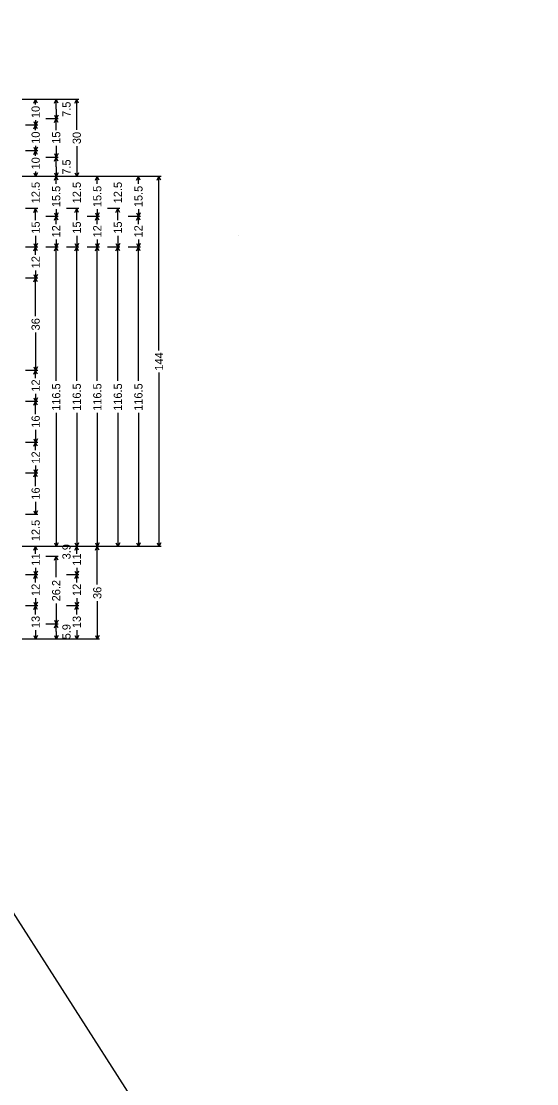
# Model space of a CAD drawing. Extents: x 667331 to 731245, y 738830 to 753817.
# Drawn here: x 723929 to 724230, y 748814 to 749434 of the extents above; entities that cross this region are included whole.
import ezdxf

# ---------------------------------------------------------------- set-up
doc = ezdxf.new("R2010")
doc.units = 0
doc.layers.add('R_SIGN', color=7, linetype='Continuous')

msp = doc.modelspace()

# ---------------------------------------------------------------- linework, layer by layer
at = {"layer": 'R_SIGN'}
for p, q in [((725910.64, 745814.78), (722956.13, 750422.85)), ((723962.15, 749388.12), (723929.15, 749388.12)), ((723938.15, 749388.12), (723930.95, 749388.12)), ((723935.87, 749385.97), (723936.95, 749388.12)), ((723936.95, 749385.15), (723936.95, 749388.12)), ((723938.02, 749385.97), (723936.95, 749388.12)), ((723950.15, 749388.12), (723942.95, 749388.12)), ((723947.87, 749385.97), (723948.95, 749388.12)), ((723948.95, 749382.49), (723948.95, 749388.12)), ((723950.02, 749385.97), (723948.95, 749388.12)), ((723959.87, 749385.97), (723960.95, 749388.12)), ((723960.95, 749370.36), (723960.95, 749388.12)), ((723962.02, 749385.97), (723960.95, 749388.12)), ((723947.87, 749379.02), (723948.95, 749376.87)), ((723948.95, 749382.49), (723948.95, 749376.87)), ((723950.02, 749379.02), (723948.95, 749376.87)), ((723938.15, 749373.12), (723930.95, 749373.12)), ((723935.87, 749375.27), (723936.95, 749373.12)), ((723935.87, 749370.97), (723936.95, 749373.12)), ((723936.95, 749376.09), (723936.95, 749373.12)), ((723938.02, 749375.27), (723936.95, 749373.12)), ((723936.95, 749370.15), (723936.95, 749373.12)), ((723938.02, 749370.97), (723936.95, 749373.12)), ((723950.15, 749376.87), (723942.95, 749376.87)), ((723947.87, 749374.72), (723948.95, 749376.87)), ((723948.95, 749370.16), (723948.95, 749376.87)), ((723950.02, 749374.72), (723948.95, 749376.87)), ((723936.95, 749361.09), (723936.95, 749358.12)), ((723948.95, 749361.08), (723948.95, 749354.37)), ((723960.95, 749360.88), (723960.95, 749343.12)), ((723938.15, 749358.12), (723930.95, 749358.12)), ((723938.15, 749358.12), (723930.95, 749358.12)), ((723935.87, 749360.27), (723936.95, 749358.12)), ((723935.87, 749355.97), (723936.95, 749358.12)), ((723938.02, 749360.27), (723936.95, 749358.12)), ((723936.95, 749355.15), (723936.95, 749358.12)), ((723938.02, 749355.97), (723936.95, 749358.12)), ((723950.15, 749354.37), (723942.95, 749354.37)), ((723950.15, 749354.37), (723942.95, 749354.37)), ((723947.87, 749356.52), (723948.95, 749354.37)), ((723947.87, 749352.22), (723948.95, 749354.37)), ((723950.02, 749356.52), (723948.95, 749354.37)), ((723948.95, 749348.74), (723948.95, 749354.37)), ((723950.02, 749352.22), (723948.95, 749354.37)), ((723948.95, 749348.74), (723948.95, 749343.12)), ((724010.15, 749343.12), (723929.15, 749343.12)), ((723962.15, 749343.12), (723929.15, 749343.12)), ((723938.15, 749343.12), (723930.95, 749343.12)), ((723938.15, 749343.12), (723930.95, 749343.12)), ((723935.87, 749345.27), (723936.95, 749343.12)), ((723936.95, 749346.09), (723936.95, 749343.12)), ((723938.02, 749345.27), (723936.95, 749343.12)), ((723950.15, 749343.12), (723942.95, 749343.12)), ((723950.15, 749343.12), (723942.95, 749343.12)), ((723947.87, 749345.27), (723948.95, 749343.12)), ((723947.87, 749340.97), (723948.95, 749343.12)), ((723950.02, 749345.27), (723948.95, 749343.12)), ((723948.95, 749338.94), (723948.95, 749343.12)), ((723950.02, 749340.97), (723948.95, 749343.12)), ((723962.15, 749343.12), (723954.95, 749343.12)), ((723959.87, 749345.27), (723960.95, 749343.12)), ((723962.02, 749345.27), (723960.95, 749343.12)), ((723974.15, 749343.12), (723966.95, 749343.12)), ((723971.87, 749340.97), (723972.95, 749343.12)), ((723972.95, 749338.94), (723972.95, 749343.12)), ((723974.02, 749340.97), (723972.95, 749343.12)), ((723986.15, 749343.12), (723978.95, 749343.12)), ((723998.15, 749343.12), (723990.95, 749343.12)), ((723995.87, 749340.97), (723996.95, 749343.12)), ((723996.95, 749338.94), (723996.95, 749343.12)), ((723998.02, 749340.97), (723996.95, 749343.12)), ((724007.87, 749340.97), (724008.95, 749343.12)), ((724008.95, 749241.56), (724008.95, 749343.12)), ((724010.02, 749340.97), (724008.95, 749343.12)), ((723938.15, 749324.41), (723930.95, 749324.41)), ((723935.87, 749322.26), (723936.95, 749324.41)), ((723936.95, 749317.7), (723936.95, 749324.41)), ((723938.02, 749322.26), (723936.95, 749324.41)), ((723948.95, 749324.08), (723948.95, 749319.91)), ((723962.15, 749324.41), (723954.95, 749324.41)), ((723959.87, 749322.26), (723960.95, 749324.41)), ((723960.95, 749317.7), (723960.95, 749324.41)), ((723962.02, 749322.26), (723960.95, 749324.41)), ((723972.95, 749324.08), (723972.95, 749319.91)), ((723986.15, 749324.41), (723978.95, 749324.41)), ((723983.87, 749322.26), (723984.95, 749324.41)), ((723984.95, 749317.7), (723984.95, 749324.41)), ((723986.02, 749322.26), (723984.95, 749324.41)), ((723996.95, 749324.08), (723996.95, 749319.91)), ((723950.15, 749319.91), (723942.95, 749319.91)), ((723947.87, 749322.05), (723948.95, 749319.91)), ((723947.87, 749317.76), (723948.95, 749319.91)), ((723950.02, 749322.05), (723948.95, 749319.91)), ((723948.95, 749315.42), (723948.95, 749319.91)), ((723950.02, 749317.76), (723948.95, 749319.91)), ((723974.15, 749319.91), (723966.95, 749319.91)), ((723971.87, 749322.05), (723972.95, 749319.91)), ((723971.87, 749317.76), (723972.95, 749319.91)), ((723974.02, 749322.05), (723972.95, 749319.91)), ((723972.95, 749315.42), (723972.95, 749319.91)), ((723974.02, 749317.76), (723972.95, 749319.91)), ((723998.15, 749319.91), (723990.95, 749319.91)), ((723995.87, 749322.05), (723996.95, 749319.91)), ((723995.87, 749317.76), (723996.95, 749319.91)), ((723998.02, 749322.05), (723996.95, 749319.91)), ((723996.95, 749315.42), (723996.95, 749319.91)), ((723998.02, 749317.76), (723996.95, 749319.91)), ((723936.95, 749308.61), (723936.95, 749301.91)), ((723948.95, 749306.39), (723948.95, 749301.91)), ((723960.95, 749308.61), (723960.95, 749301.91)), ((723972.95, 749306.39), (723972.95, 749301.91)), ((723984.95, 749308.61), (723984.95, 749301.91)), ((723996.95, 749306.39), (723996.95, 749301.91)), ((724055.45, 749308.62), (724055.45, 749308.62)), ((724055.45, 749308.62), (724055.45, 749308.62)), ((724055.45, 749308.62), (724055.45, 749308.62)), ((724055.45, 749308.62), (724055.45, 749308.62)), ((723938.15, 749301.91), (723930.95, 749301.91)), ((723935.87, 749304.05), (723936.95, 749301.91)), ((723935.87, 749299.76), (723936.95, 749301.91)), ((723938.02, 749304.05), (723936.95, 749301.91)), ((723936.95, 749297.42), (723936.95, 749301.91)), ((723938.02, 749299.76), (723936.95, 749301.91)), ((723950.15, 749301.91), (723942.95, 749301.91)), ((723950.15, 749301.91), (723942.95, 749301.91)), ((723947.87, 749304.05), (723948.95, 749301.91)), ((723947.87, 749299.76), (723948.95, 749301.91)), ((723950.02, 749304.05), (723948.95, 749301.91)), ((723948.95, 749223.87), (723948.95, 749301.91)), ((723950.02, 749299.76), (723948.95, 749301.91)), ((723962.15, 749301.91), (723954.95, 749301.91)), ((723962.15, 749301.91), (723954.95, 749301.91)), ((723959.87, 749304.05), (723960.95, 749301.91)), ((723959.87, 749299.76), (723960.95, 749301.91)), ((723962.02, 749304.05), (723960.95, 749301.91)), ((723960.95, 749223.87), (723960.95, 749301.91)), ((723962.02, 749299.76), (723960.95, 749301.91)), ((723974.15, 749301.91), (723966.95, 749301.91)), ((723974.15, 749301.91), (723966.95, 749301.91)), ((723971.87, 749304.05), (723972.95, 749301.91)), ((723971.87, 749299.76), (723972.95, 749301.91)), ((723974.02, 749304.05), (723972.95, 749301.91)), ((723972.95, 749223.87), (723972.95, 749301.91)), ((723974.02, 749299.76), (723972.95, 749301.91)), ((723986.15, 749301.91), (723978.95, 749301.91)), ((723986.15, 749301.91), (723978.95, 749301.91)), ((723983.87, 749304.05), (723984.95, 749301.91)), ((723983.87, 749299.76), (723984.95, 749301.91)), ((723986.02, 749304.05), (723984.95, 749301.91)), ((723984.95, 749223.87), (723984.95, 749301.91)), ((723986.02, 749299.76), (723984.95, 749301.91)), ((723998.15, 749301.91), (723990.95, 749301.91)), ((723998.15, 749301.91), (723990.95, 749301.91)), ((723995.87, 749304.05), (723996.95, 749301.91)), ((723995.87, 749299.76), (723996.95, 749301.91)), ((723998.02, 749304.05), (723996.95, 749301.91)), ((723996.95, 749223.87), (723996.95, 749301.91)), ((723998.02, 749299.76), (723996.95, 749301.91)), ((723935.87, 749286.05), (723936.95, 749283.91)), ((723936.95, 749288.39), (723936.95, 749283.91)), ((723938.02, 749286.05), (723936.95, 749283.91)), ((723938.15, 749283.91), (723930.95, 749283.91)), ((723935.87, 749281.76), (723936.95, 749283.91)), ((723936.95, 749261.69), (723936.95, 749283.91)), ((723938.02, 749281.76), (723936.95, 749283.91)), ((723936.95, 749252.13), (723936.95, 749229.91)), ((723935.87, 749232.05), (723936.95, 749229.91)), ((723938.02, 749232.05), (723936.95, 749229.91)), ((723938.15, 749229.91), (723930.95, 749229.91)), ((723935.87, 749227.76), (723936.95, 749229.91)), ((723936.95, 749225.42), (723936.95, 749229.91)), ((723938.02, 749227.76), (723936.95, 749229.91)), ((724008.95, 749228.68), (724008.95, 749127.12)), ((723938.15, 749211.91), (723930.95, 749211.91)), ((723935.87, 749214.05), (723936.95, 749211.91)), ((723935.87, 749209.76), (723936.95, 749211.91)), ((723936.95, 749216.39), (723936.95, 749211.91)), ((723938.02, 749214.05), (723936.95, 749211.91)), ((723936.95, 749204.47), (723936.95, 749211.91)), ((723938.02, 749209.76), (723936.95, 749211.91)), ((723948.95, 749205.16), (723948.95, 749127.12)), ((723960.95, 749205.16), (723960.95, 749127.12)), ((723972.95, 749205.16), (723972.95, 749127.12)), ((723984.95, 749205.16), (723984.95, 749127.12)), ((723996.95, 749205.16), (723996.95, 749127.12)), ((723936.95, 749195.34), (723936.95, 749187.91)), ((723938.15, 749187.91), (723930.95, 749187.91)), ((723935.87, 749190.05), (723936.95, 749187.91)), ((723935.87, 749185.76), (723936.95, 749187.91)), ((723938.02, 749190.05), (723936.95, 749187.91)), ((723936.95, 749183.42), (723936.95, 749187.91)), ((723938.02, 749185.76), (723936.95, 749187.91)), ((723936.95, 749174.39), (723936.95, 749169.91)), ((723938.15, 749169.91), (723930.95, 749169.91)), ((723935.87, 749172.05), (723936.95, 749169.91)), ((723935.87, 749167.76), (723936.95, 749169.91)), ((723938.02, 749172.05), (723936.95, 749169.91)), ((723936.95, 749162.47), (723936.95, 749169.91)), ((723938.02, 749167.76), (723936.95, 749169.91)), ((723936.95, 749153.34), (723936.95, 749145.91)), ((723938.15, 749145.91), (723930.95, 749145.91)), ((723938.15, 749145.91), (723930.95, 749145.91)), ((723935.87, 749148.05), (723936.95, 749145.91)), ((723938.02, 749148.05), (723936.95, 749145.91)), ((724010.15, 749127.12), (723929.15, 749127.12)), ((723974.15, 749127.12), (723929.15, 749127.12)), ((723938.15, 749127.12), (723930.95, 749127.12)), ((723938.15, 749127.12), (723930.95, 749127.12)), ((723935.87, 749124.97), (723936.95, 749127.12)), ((723936.95, 749122.92), (723936.95, 749127.12)), ((723938.02, 749124.97), (723936.95, 749127.12)), ((723950.15, 749127.12), (723942.95, 749127.12)), ((723950.15, 749127.12), (723942.95, 749127.12)), ((723947.87, 749129.27), (723948.95, 749127.12)), ((723950.02, 749129.27), (723948.95, 749127.12)), ((723962.15, 749127.12), (723954.95, 749127.12)), ((723962.15, 749127.12), (723954.95, 749127.12)), ((723959.87, 749129.27), (723960.95, 749127.12)), ((723959.87, 749124.97), (723960.95, 749127.12)), ((723962.02, 749129.27), (723960.95, 749127.12)), ((723960.95, 749122.92), (723960.95, 749127.12)), ((723962.02, 749124.97), (723960.95, 749127.12)), ((723974.15, 749127.12), (723966.95, 749127.12)), ((723971.87, 749129.27), (723972.95, 749127.12)), ((723971.87, 749124.97), (723972.95, 749127.12)), ((723974.02, 749129.27), (723972.95, 749127.12)), ((723972.95, 749104.9), (723972.95, 749127.12)), ((723974.02, 749124.97), (723972.95, 749127.12)), ((723986.15, 749127.12), (723978.95, 749127.12)), ((723983.87, 749129.27), (723984.95, 749127.12)), ((723986.02, 749129.27), (723984.95, 749127.12)), ((723998.15, 749127.12), (723990.95, 749127.12)), ((723995.87, 749129.27), (723996.95, 749127.12)), ((723998.02, 749129.27), (723996.95, 749127.12)), ((724007.87, 749129.27), (724008.95, 749127.12)), ((724010.02, 749129.27), (724008.95, 749127.12)), ((723950.15, 749121.31), (723942.95, 749121.31)), ((723947.87, 749119.16), (723948.95, 749121.31)), ((723948.95, 749109.29), (723948.95, 749121.31)), ((723950.02, 749119.16), (723948.95, 749121.31)), ((723935.87, 749112.77), (723936.95, 749110.62)), ((723936.95, 749114.82), (723936.95, 749110.62)), ((723938.02, 749112.77), (723936.95, 749110.62)), ((723959.87, 749112.77), (723960.95, 749110.62)), ((723960.95, 749114.82), (723960.95, 749110.62)), ((723962.02, 749112.77), (723960.95, 749110.62)), ((723938.15, 749110.62), (723930.95, 749110.62)), ((723935.87, 749108.47), (723936.95, 749110.62)), ((723936.95, 749106.14), (723936.95, 749110.62)), ((723938.02, 749108.47), (723936.95, 749110.62)), ((723962.15, 749110.62), (723954.95, 749110.62)), ((723959.87, 749108.47), (723960.95, 749110.62)), ((723960.95, 749106.14), (723960.95, 749110.62)), ((723962.02, 749108.47), (723960.95, 749110.62)), ((723935.87, 749094.77), (723936.95, 749092.62)), ((723936.95, 749097.1), (723936.95, 749092.62)), ((723938.02, 749094.77), (723936.95, 749092.62)), ((723948.95, 749093.95), (723948.95, 749081.93)), ((723959.87, 749094.77), (723960.95, 749092.62)), ((723960.95, 749097.1), (723960.95, 749092.62)), ((723962.02, 749094.77), (723960.95, 749092.62)), ((723972.95, 749095.34), (723972.95, 749073.12)), ((723938.15, 749092.62), (723930.95, 749092.62)), ((723938.15, 749092.62), (723930.95, 749092.62)), ((723935.87, 749090.47), (723936.95, 749092.62)), ((723936.95, 749087.41), (723936.95, 749092.62)), ((723938.02, 749090.47), (723936.95, 749092.62)), ((723962.15, 749092.62), (723954.95, 749092.62)), ((723962.15, 749092.62), (723954.95, 749092.62)), ((723959.87, 749090.47), (723960.95, 749092.62)), ((723960.95, 749087.41), (723960.95, 749092.62)), ((723962.02, 749090.47), (723960.95, 749092.62)), ((723950.15, 749081.93), (723942.95, 749081.93)), ((723950.15, 749081.93), (723942.95, 749081.93)), ((723947.87, 749084.08), (723948.95, 749081.93)), ((723947.87, 749079.78), (723948.95, 749081.93)), ((723950.02, 749084.08), (723948.95, 749081.93)), ((723948.95, 749077.52), (723948.95, 749081.93)), ((723950.02, 749079.78), (723948.95, 749081.93)), ((723935.87, 749075.27), (723936.95, 749073.12)), ((723936.95, 749078.33), (723936.95, 749073.12)), ((723938.02, 749075.27), (723936.95, 749073.12)), ((723947.87, 749075.27), (723948.95, 749073.12)), ((723948.95, 749077.52), (723948.95, 749073.12)), ((723950.02, 749075.27), (723948.95, 749073.12)), ((723959.87, 749075.27), (723960.95, 749073.12)), ((723960.95, 749078.33), (723960.95, 749073.12)), ((723962.02, 749075.27), (723960.95, 749073.12)), ((723971.87, 749075.27), (723972.95, 749073.12)), ((723974.02, 749075.27), (723972.95, 749073.12)), ((723974.15, 749073.12), (723929.15, 749073.12)), ((723938.15, 749073.12), (723930.95, 749073.12)), ((723950.15, 749073.12), (723942.95, 749073.12)), ((723962.15, 749073.12), (723954.95, 749073.12))]:
    msp.add_line(p, q, dxfattribs=at)

# ---------------------------------------------------------------- texts
for s, p in [('7.5', (723957.35, 749377.97)), ('10', (723939.35, 749377.29)), ('10', (723939.35, 749362.29)), ('15', (723951.35, 749362.28)), ('30', (723963.35, 749362.08)), ('10', (723939.35, 749347.29)), ('7.5', (723957.35, 749344.22)), ('12.5', (723939.35, 749327.53)), ('15.5', (723951.35, 749325.28)), ('12.5', (723963.35, 749327.53)), ('15.5', (723975.35, 749325.28)), ('12.5', (723987.35, 749327.53)), ('15.5', (723999.35, 749325.28)), ('15', (723939.35, 749309.81)), ('12', (723951.35, 749307.59)), ('15', (723963.35, 749309.81)), ('12', (723975.35, 749307.59)), ('15', (723987.35, 749309.81)), ('12', (723999.35, 749307.59)), ('12', (723939.35, 749289.59)), ('36', (723939.35, 749253.33)), ('144', (724011.35, 749229.88)), ('12', (723939.35, 749217.59)), ('116.5', (723951.35, 749206.36)), ('116.5', (723963.35, 749206.36)), ('116.5', (723975.35, 749206.36)), ('116.5', (723987.35, 749206.36)), ('116.5', (723999.35, 749206.36)), ('16', (723939.35, 749196.54)), ('12', (723939.35, 749175.59)), ('16', (723939.35, 749154.54)), ('12.5', (723939.35, 749130.28)), ('3.9', (723957.35, 749119.69)), ('11', (723939.35, 749116.02)), ('11', (723963.35, 749116.02)), ('26.2', (723951.35, 749095.15)), ('12', (723939.35, 749098.3)), ('12', (723963.35, 749098.3)), ('36', (723975.35, 749096.54)), ('13', (723939.35, 749079.53)), ('5.9', (723957.35, 749072.99)), ('13', (723963.35, 749079.53))]:
    msp.add_text(s, height=4.8, rotation=90.00021, dxfattribs=at).set_placement(p)

doc.saveas('drawing.dxf')
